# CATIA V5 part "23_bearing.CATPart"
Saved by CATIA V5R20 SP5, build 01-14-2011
Part number: 23_bearing
Bounding box of the stored display mesh (mm): x -19.995 to 19.995, y -7 to 5, z -19.979 to 19.979
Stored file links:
  C:\Documents and Settings\anizard\Bureau\13\23_bearing.CATPart
  C:\Documents and Settings\anizard\Bureau\13\anizard.CATProduct
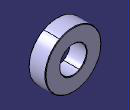
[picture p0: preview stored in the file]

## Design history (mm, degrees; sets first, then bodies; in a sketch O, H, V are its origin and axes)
Set1
  Plane1 to Plane3: linked copy from another document
  Line1: linked copy from another document
  Point1: linked copy from another document
  Point2: linked copy from another document
Body1 (main body)
  Sketch1 on Plane1, origin (0, 0, 0), H (0, 1, 0), V (0, 0, 1)
    line L1 (-6.6464, 20) -> (4.6464, 20)
    line L2 (5, 19.6464) -> (5, 9.8786)
    line L3 (4.6464, 9.525) -> (-6.6464, 9.525)
    line L4 (-7, 9.8786) -> (-7, 19.6464)
    reference intersected line E1 through (-7, 0) direction (0, 1) from Plane2
    reference intersected line E2 through (5, 0) direction (0, 1) from Plane3
    reference projected point E3 (0, 9.525) from Point1
    reference projected point E4 (0, 20) from Point2
    line L5 (5, 9.8786) -> (4.6464, 9.525)
    line L6 (-6.6464, 9.525) -> (-7, 9.8786)
    line L7 (-6.6464, 20) -> (-7, 19.6464)
    line L8 (4.6464, 20) -> (5, 19.6464)
    angle L2 L5 = 45
    length L5 = 0.5
    angle L3 L6 = 45
    length L6 = 0.5
    angle L1 L7 = 45
    length L7 = 0.5
    angle L1 L8 = 45
    length L8 = 0.5
    horizontal: L1 H, L3 H
    vertical: L2 V, L4 V
    coincidence: L4 E1, E2 L2, E3 L3, E4 L1
  Shaft1: profile Sketch1, axis Line1, angle 360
